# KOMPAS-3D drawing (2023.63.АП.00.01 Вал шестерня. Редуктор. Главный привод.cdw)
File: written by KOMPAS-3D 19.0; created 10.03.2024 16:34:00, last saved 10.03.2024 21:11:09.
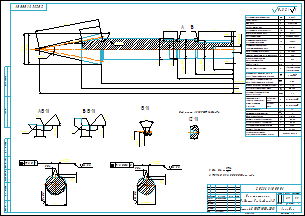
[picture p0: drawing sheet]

Sheet 1: A2, landscape

Document properties: Автор: mail.maksim@mail.ru; Знак неуказанной шероховатости: 4; Параметр неуказанной шероховатости: Rz3,2; Масса: 2.903

Title block, sheet 1: Наименование: Вал шестерня. / Редуктор. Главный привод; designation: 2023.63.АП.00.01; Материал: Сталь 45 ГОСТ 1050-2013; Масса: 2,9; Количество листов документа: 1; organisation: АгроПак; Форматы листов документа: A2; stored path: O:\Самозанятый. Полынский М.И\Агропак\03 Проекты 2023 года\2023.63.АП.00.00 Ремкомплект редуктора. Шестерня и вал-шестерня\2023.63.АП Чертежи\2023.63.АП.00.01 Вал шестерня. Редуктор. Главный привод.cdw; Разработал: Полынский; Утвердил: Гордиенко

Views: Вид и метод обработки, Выносной элемент (канавка под выход шлиф. круга), Выносной элемент
Referenced files in C:\Users\mailm\AppData\Roaming\Ascon\KOMPAS-3D\19\SHAFT\: Деталь (типа вал-шестерня).m3d
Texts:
  Ячейка таблицы
  Обозначение чертежа
  сопряженного зубчатого колеса
  Внешняя высота зуба
  Средний делительный диаметр
  Среднее конусное расстояние
  Внешнее конусное расстояние
  Угол конуса впадин
  Внешний окружной модуль
  Межосевой угол
  Относительные
  размеры суммарного
  пятна контакта
  в передаче
  Гарантированный боковой
  зазор в передаче
  Предельное отклонение шага
  Допуск на биение зубчатого венца
  Высота до делительной хорды
  зуба в измерительном сечении
  Делительная толщина зуба по
  хорде в измерительном сечении
  Развод резцов
  Номинальный диаметр
  зуборезной головки
  Степень точности по ГОСТ 1758-81
  Угол делительного конуса
  Коэффициент изменения
  расчетной толщины зуба
  Коэффициент смещения
  средний нормальный
  Исходный контур
  Направление линии зуба
  Средний угол наклона зубьев
  Осевая форма зуба
  Тип зуба
  Число зубьев
  Средний нормальный модуль
  по длине
  зуба
  по высоте
  Symbol
  m te
  f Pt
  не менее 55%
  не менее 50%
  двухсторонний
  однономерный
  ГОСТ 16202-81
  левое
  Круговой
  Таблица параметров
  Ra 0,8
  Отв. центр. A3,15 ГОСТ 14034-74
  Выносной элемент (посадочное место под уплотнительное резиновое кольцо для резьбового соединения)
  Rz3,2
  Rz3,2 ( )
  gliv
  EditDiam#9571142@DIAMNEXT()@1
Dimensions and other numbers on the sheet: 60,832; 60; 125,32; 40; 3,023; 258,966; 298; 380,715; 12 43'56"; 78 57'33"; 12; 110; 75; 1,5; 1,6; 5; 65; 28; 36,513; 35; 2023.63.АП.00.02; 10,427; 40,34; 105,32; 8 37'57"; 6; 0,1; 0,05; 6,153; 6,711 -0,092 -0,192; 1; 200; 8-B; 11 02'27"; -0,4319; 0,5518; 8; 4,3669; 0,5; 0,394; 36,0125; 3; 34,5; 39,026; 38,16; 10; 1:1; 2,9; 2023.63.АП.00.01; 2023.63.АП.00.01-

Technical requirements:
  ТВЧ h 0,8...1,2; 50...55 HRC Э  по зубу.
